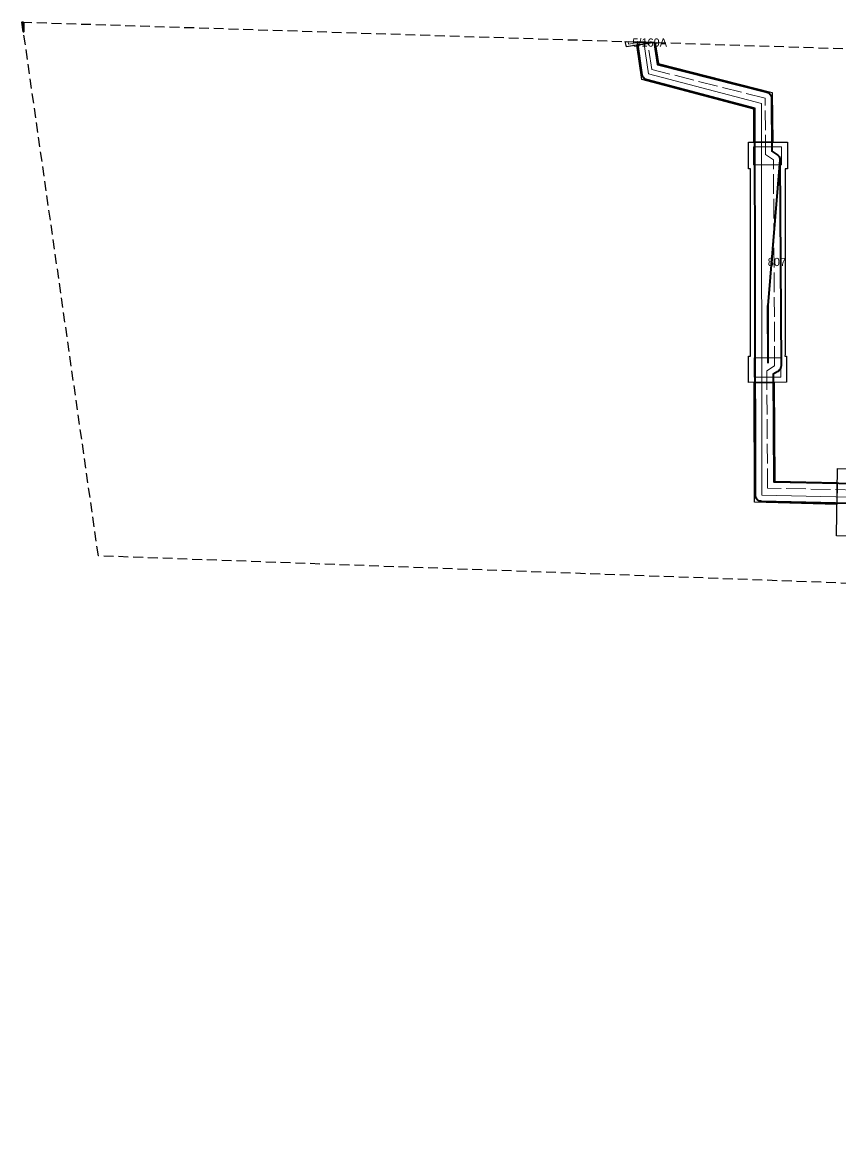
# Model space of a CAD drawing. Extents: x -451331 to -449998, y -1101254 to -1101132.
# Drawn here: x -451330.5 to -451240.9, y -1101253.5 to -1101132.1 of the extents above; entities that cross this region are included whole.
import ezdxf

# ---------------------------------------------------------------- set-up
doc = ezdxf.new("R2010")
doc.units = 0
doc.header["$LTSCALE"] = 0.36
doc.linetypes.add('LONG_DASHED', pattern=[7.5, 6, -1.5])
doc.linetypes.add('MEDIUM_DASHED', pattern=[4.5, 3, -1.5])
for name, color, linetype, lineweight in [('2', 7, 'Continuous', 13), ('3', 7, 'Continuous', 25), ('62', 7, 'MEDIUM_DASHED', 25), ('8', 7, 'Continuous', 35)]:
    doc.layers.add(name, color=color, linetype=linetype, lineweight=lineweight)

msp = doc.modelspace()

# ---------------------------------------------------------------- linework, layer by layer
at = {"layer": '2'}
msp.add_lwpolyline([(-451262.272, -1101134.293), (-451261.769, -1101137.772), (-451249.372, -1101141.048), (-451249.333, -1101184.03), (-451239.584, -1101184.268)], dxfattribs=at)
at = {"layer": '2', "linetype": 'LONG_DASHED'}
msp.add_lwpolyline([(-451239.081, -1101183.474), (-451248.694, -1101183.268), (-451248.77, -1101170.376), (-451247.913, -1101169.853), (-451248.046, -1101147.205), (-451248.909, -1101146.643), (-451248.945, -1101140.461), (-451261.395, -1101137.3), (-451261.842, -1101134.307)], dxfattribs=at)
at = {"layer": '3'}
for points in [[(-451264.189, -1101134.82), (-451264.317, -1101134.227), (-451261.319, -1101134.323)], [(-451263.034, -1101134.619), (-451261.319, -1101134.323), (-451261.041, -1101134.332), (-451260.683, -1101136.655), (-451248.179, -1101139.83), (-451248.114, -1101145.284), (-451250.197, -1101145.284), (-451250.188, -1101141.659), (-451262.484, -1101138.41)], [(-451246.77, -1101148.217), (-451246.77, -1101168.572), (-451246.778, -1101168.762), (-451246.601, -1101168.761), (-451246.601, -1101171.645), (-451250.788, -1101171.671), (-451250.788, -1101168.794), (-451250.58, -1101168.792), (-451250.579, -1101168.572), (-451250.579, -1101148.217), (-451250.782, -1101148.217), (-451250.782, -1101145.28), (-451246.496, -1101145.28), (-451246.496, -1101148.217)], [(-451247.962, -1101171.653), (-451247.899, -1101182.485), (-451241.048, -1101182.655), (-451241.084, -1101185.05), (-451250.133, -1101184.81), (-451250.144, -1101171.666)], [(-451241.135, -1101188.5), (-451241.025, -1101181.101), (-451233.439, -1101181.214), (-451233.549, -1101188.614)]]:
    msp.add_lwpolyline(points, close=True, dxfattribs=at)
at = {"layer": '3', "lineweight": 13}
for points in [[(-451262.663, -1101134.28), (-451263.953, -1101134.501), (-451264.01, -1101134.237)], [(-451250.222, -1101145.8), (-451247.163, -1101145.789), (-451247.163, -1101147.758), (-451250.253, -1101147.758)], [(-451250.144, -1101168.971), (-451247.237, -1101168.947), (-451247.224, -1101171.086), (-451250.157, -1101171.099)]]:
    msp.add_lwpolyline(points, close=True, dxfattribs=at)
at = {"layer": '62'}
msp.add_lwpolyline([(-450786.261, -1101210.25), (-451322.174, -1101190.711), (-451330.547, -1101132.096), (-450766.722, -1101150.239), (-450459.689, -1101190.711), (-449997.743, -1101194.898), (-449997.743, -1101249.327), (-450456.897, -1101253.514)], close=True, dxfattribs=at)
at = {"layer": '8'}
msp.add_lwpolyline([(-451330.394, -1101132.101), (-451330.394, -1101133.17), (-451330.547, -1101132.096)], close=True, dxfattribs=at)
for points in [[(-451239.601, -1101184.967), (-451249.351, -1101184.729), (-451249.471, -1101184.716), (-451249.586, -1101184.682), (-451249.694, -1101184.63), (-451249.791, -1101184.559), (-451249.875, -1101184.474), (-451249.943, -1101184.375), (-451249.993, -1101184.266), (-451250.023, -1101184.15), (-451250.034, -1101184.03), (-451250.071, -1101141.587), (-451261.947, -1101138.448), (-451262.057, -1101138.409), (-451262.159, -1101138.352), (-451262.25, -1101138.279), (-451262.328, -1101138.192), (-451262.39, -1101138.093), (-451262.435, -1101137.986), (-451262.461, -1101137.872), (-451262.983, -1101134.27), (-451261.131, -1101134.33), (-451260.772, -1101136.736), (-451248.772, -1101139.783), (-451248.664, -1101139.82), (-451248.562, -1101139.875), (-451248.472, -1101139.945), (-451248.393, -1101140.03), (-451248.33, -1101140.126), (-451248.284, -1101140.231), (-451248.255, -1101140.342), (-451248.245, -1101140.457), (-451248.211, -1101146.262), (-451247.663, -1101146.619), (-451247.572, -1101146.689), (-451247.494, -1101146.774), (-451247.431, -1101146.87), (-451247.384, -1101146.975), (-451247.356, -1101147.087), (-451247.346, -1101147.201), (-451248.652, -1101163.211), (-451248.646, -1101169.481), (-451248.615, -1101169.462), (-451248.652, -1101163.211)], [(-451247.346, -1101147.201), (-451247.213, -1101169.851), (-451247.223, -1101169.971), (-451247.253, -1101170.086), (-451247.302, -1101170.195), (-451247.369, -1101170.294), (-451247.452, -1101170.38), (-451247.549, -1101170.451), (-451248.067, -1101170.767), (-451247.998, -1101182.583), (-451239.066, -1101182.774)]]:
    msp.add_lwpolyline(points, dxfattribs=at)

# ---------------------------------------------------------------- texts
at = {"layer": '3'}
for s, p in [('5/169A ', (-451263.542, -1101134.788)), ('807 ', (-451248.673, -1101158.883))]:
    msp.add_text(s, height=0.9, dxfattribs=at).set_placement(p)

doc.saveas('drawing.dxf')
